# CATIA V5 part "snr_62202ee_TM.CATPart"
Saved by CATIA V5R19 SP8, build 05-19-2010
Part number: snr_62202ee_1_1
Nomenclature: 39_b
Source: Unknown
Description: PART-snr_62202ee_1_1-DESC
Bounding box of the stored display mesh (mm): x 0 to 14, y -17.5 to 17.5, z -17.5 to 17.5
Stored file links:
  C:\Users\rphgr\Desktop\0_Tapis_TC520B_vitesse\snr_62202ee_TM.CATPart
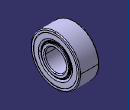
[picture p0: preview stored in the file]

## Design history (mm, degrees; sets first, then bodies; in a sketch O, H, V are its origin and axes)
AxisSystem1: origin (0, 0, 0), X (1, 0, 0), Y (0, 1, 0), Z (0, 0, 1)
Body1 "snr_62202ee_1_1" (main body)
  Solid1: solid without history
Body2 "snr_62202ee_1_2"
  Solid2: solid without history
Body3 "snr_62202ee_1_3"
  Solid3: solid without history
Body4 "snr_62202ee_1_4"
  Solid4: solid without history
Body5 "snr_62202ee_1_5"
  Solid5: solid without history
